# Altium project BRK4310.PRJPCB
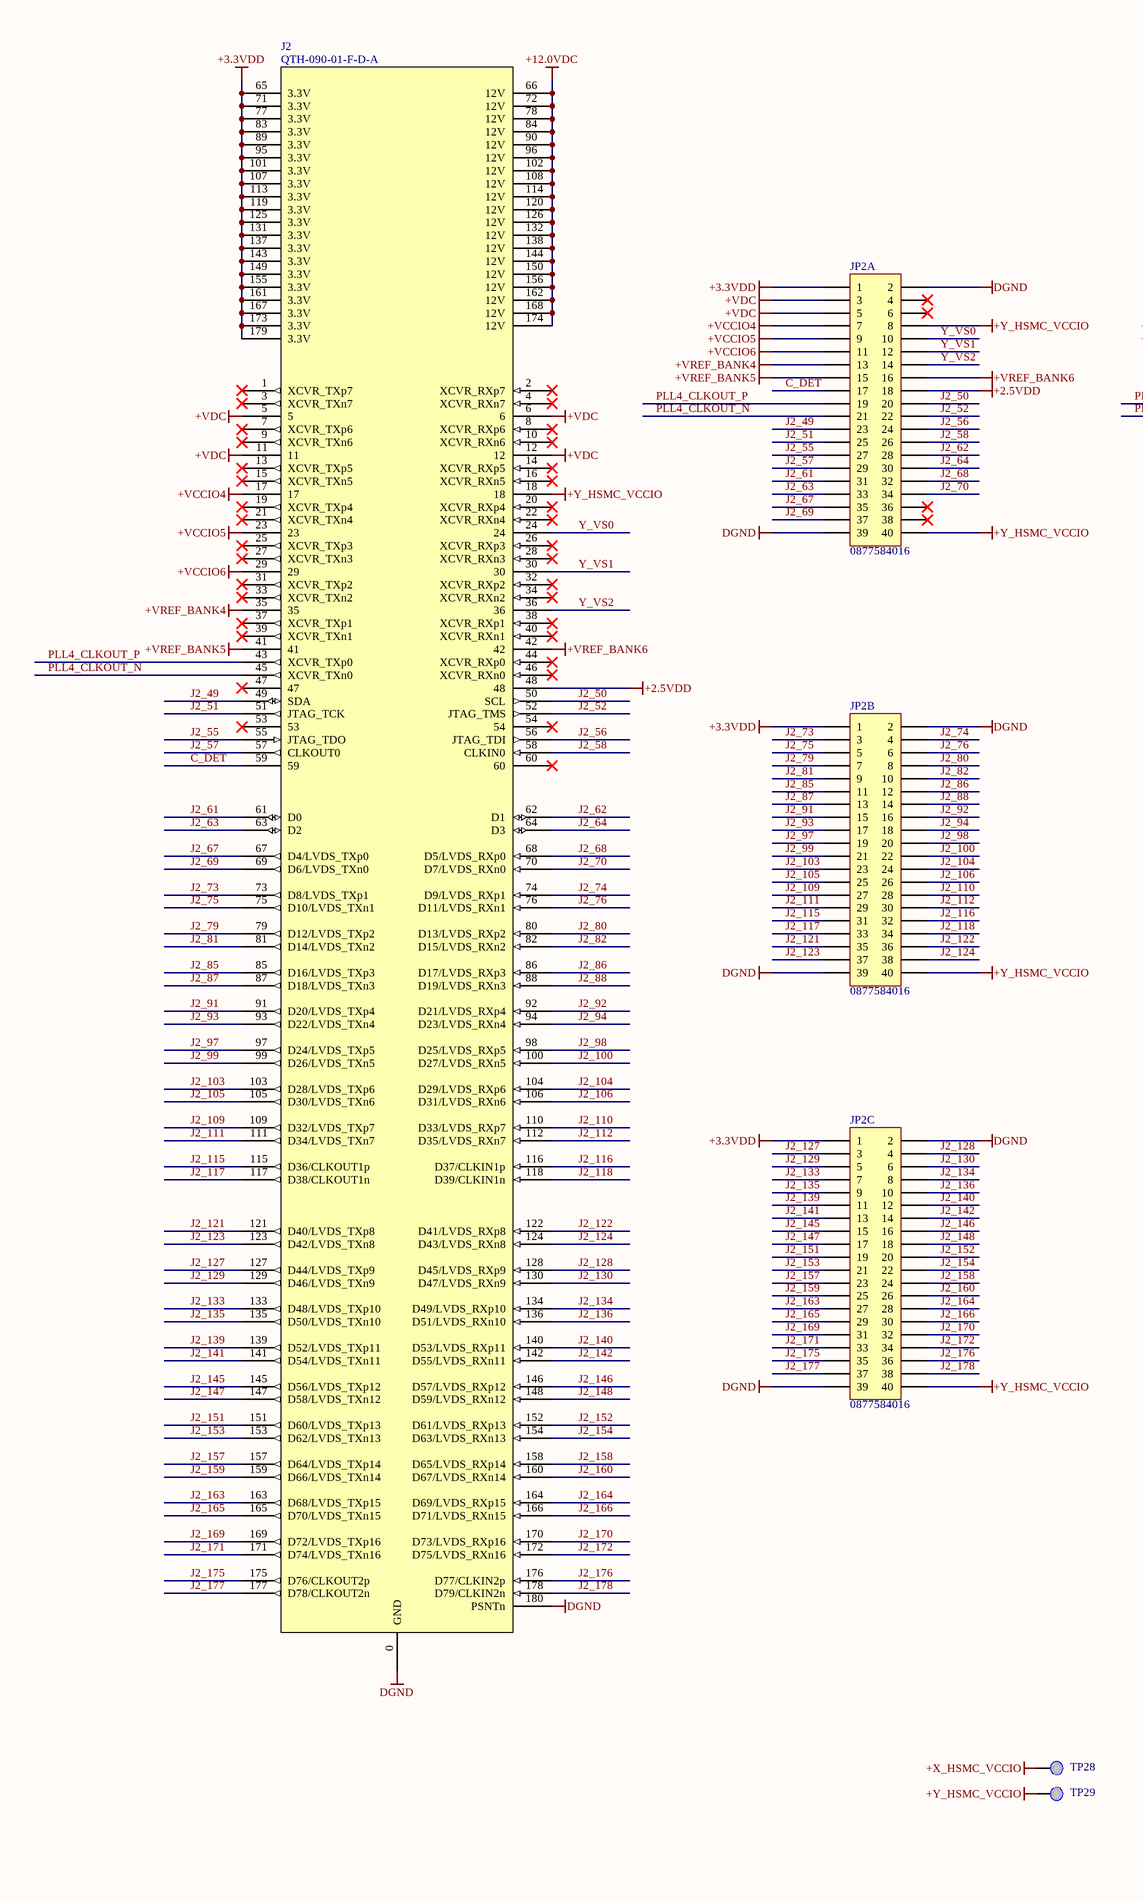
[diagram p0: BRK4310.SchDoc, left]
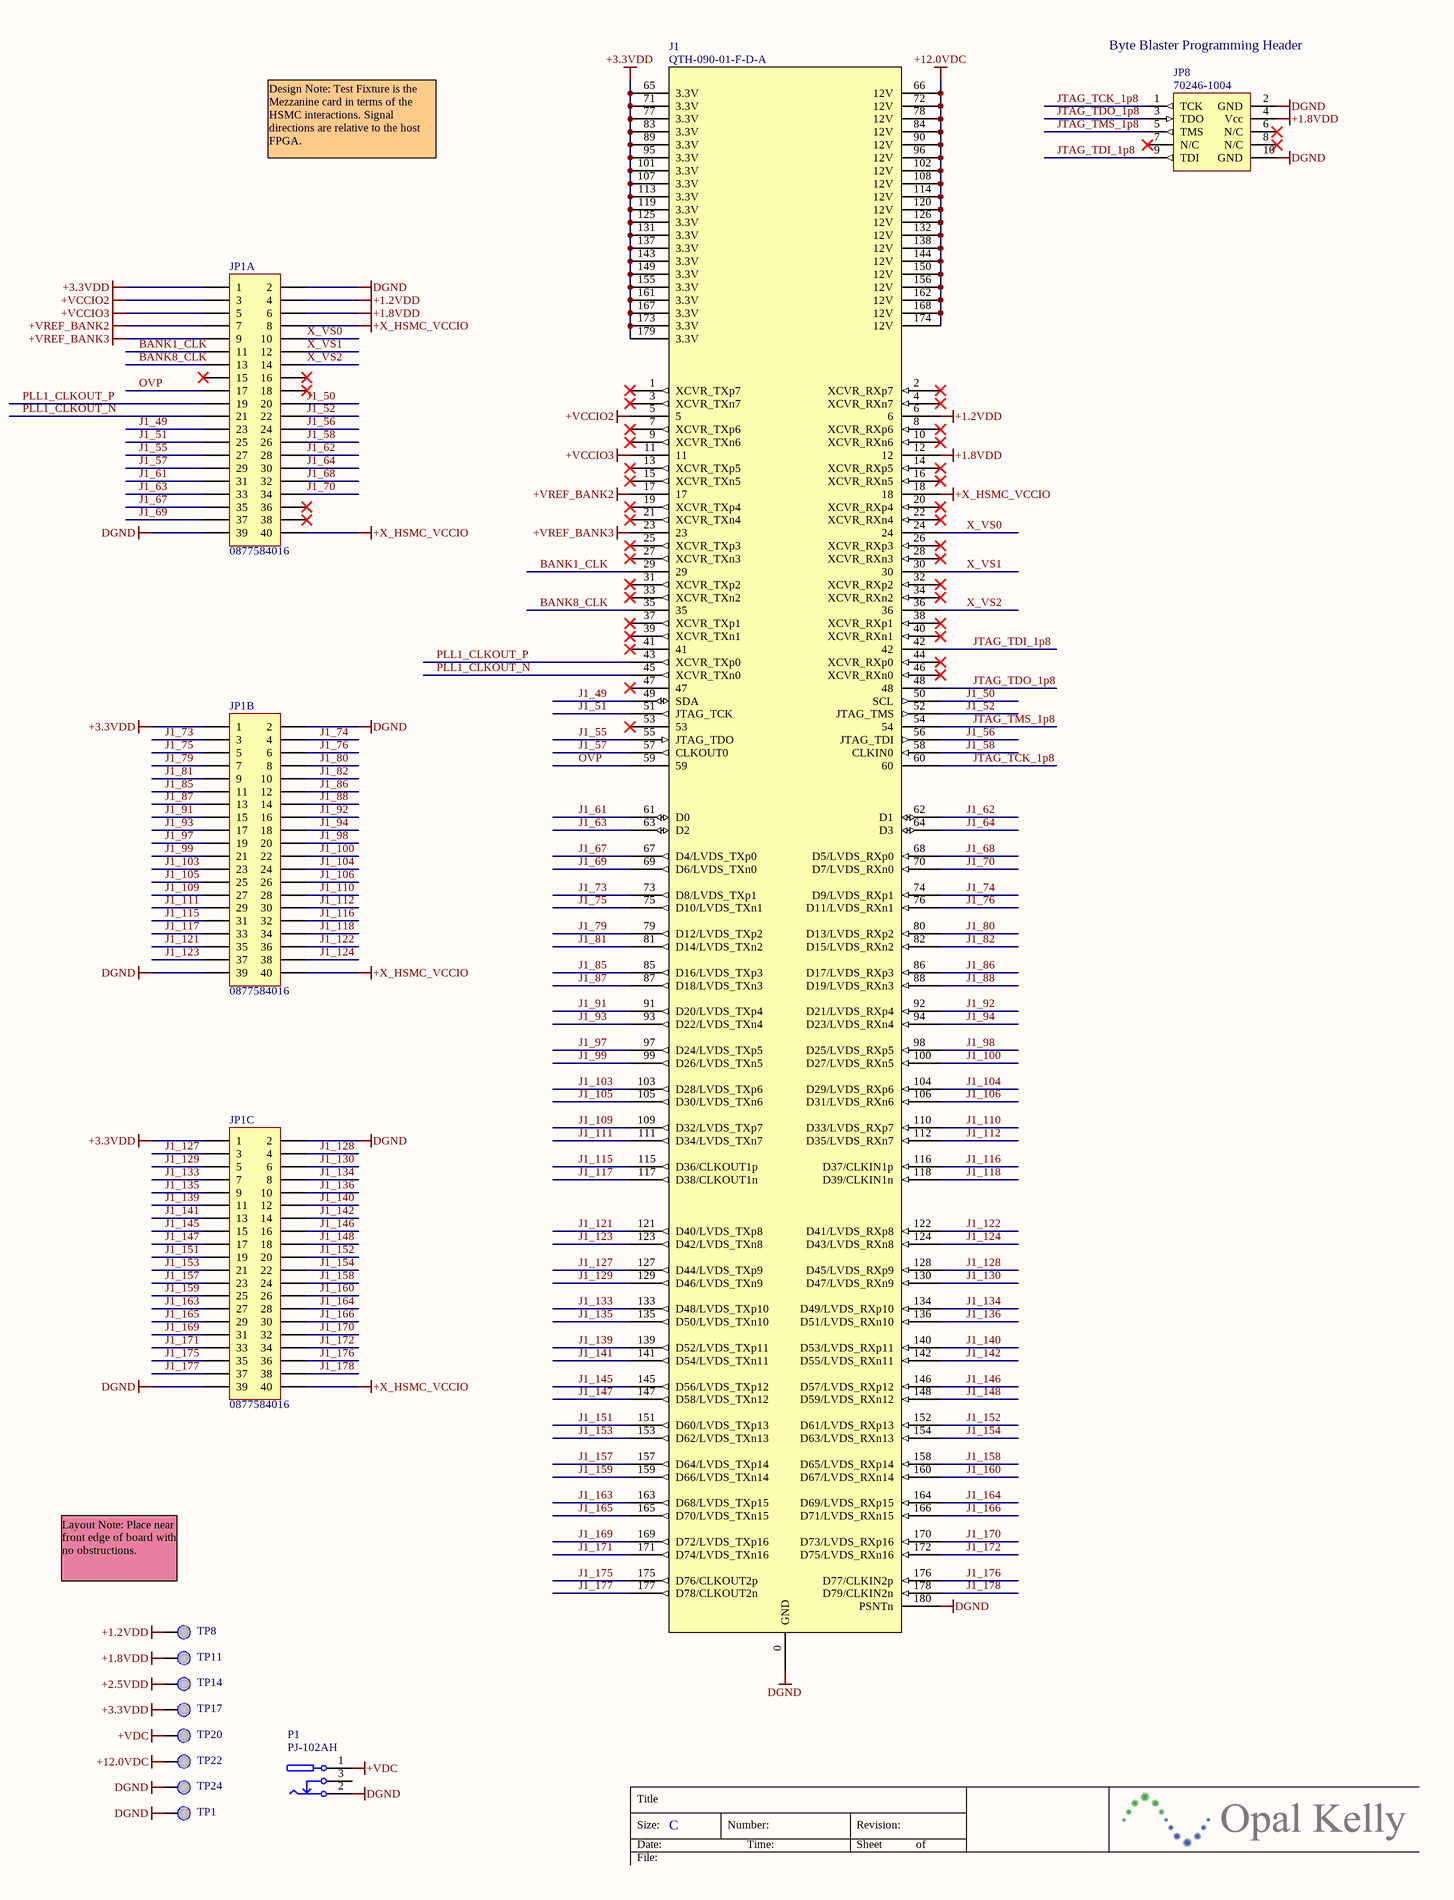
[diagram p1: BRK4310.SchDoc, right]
1 sheet, 20 parts. Net scope: global (net labels, ports and power ports of the same name join across sheets).
Board file: BRK4310.PcbDoc

## Sheet BRK4310.SchDoc: BRK4310
size C; Author: Jake Janovetz; Organization: Opal Kelly; Address1: 13500 SW 72nd Ave, STE 120; Address2: Portland, OR 97223; Address4: http://www.opalkelly.com; DocumentNumber: xxx; Revision: 1; SheetNumber: 1; SheetTotal: 1; PageSetup: Record=PageOptions¦CenterHorizontal=True¦CenterVertical=True¦PrintScale=0.53¦XCorrection=1.00¦YCorrection=1.00¦PrintKind=0¦BorderSize=5000000¦LeftOffset=0¦BottomOffset=0¦Orientation=2¦PaperLength=1000¦PaperWidth=1000¦Scale=100¦PaperSource=7¦PrintQuality=-4¦MediaType=1¦DitherType=10¦PaperKind=Letter¦PrintScaleMode=1

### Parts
J1  QTH-090-01-F-D-A  [QTH-090-01-X-D]
J2  QTH-090-01-F-D-A  [QTH-090-01-X-D]
JP1A  0877584016  [HDR2X20-2MM]
JP1B  0877584016  [HDR2X20-2MM]
JP1C  0877584016  [HDR2X20-2MM]
JP2A  0877584016  [HDR2X20-2MM]
JP2B  0877584016  [HDR2X20-2MM]
JP2C  0877584016  [HDR2X20-2MM]
JP8  70246-1004  [HDR2X5-SHRD]
P1  PJ-102AH  [CUI-PJ102A]
TP1  DGND  [TP_MED]  (value not drawn)
TP8  +1.2VDD  [TP_MED]  (value not drawn)
TP11  +1.8VDD  [TP_MED]  (value not drawn)
TP14  +2.5VDD  [TP_MED]  (value not drawn)
TP17  +3.3VDD  [TP_MED]  (value not drawn)
TP20  +VDC  [TP_MED]  (value not drawn)
TP22  +12.0VDC  [TP_MED]  (value not drawn)
TP24  DGND  [TP_MED]  (value not drawn)
TP28  +J1_VCCIO  [TP_MED]  (value not drawn)
TP29  +J2_VCCIO  [TP_MED]  (value not drawn)

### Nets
+1.2VDD: J1.6 JP1A.4 TP8.1(PIN)
+1.8VDD: J1.12 JP1A.6 JP8.4(Vcc) TP11.1(PIN)
+2.5VDD: J2.48 JP2A.18 TP14.1(PIN)
+3.3VDD: J1.65(3.3V) J1.71(3.3V) J1.77(3.3V) J1.83(3.3V) J1.89(3.3V) J1.95(3.3V) J1.101(3.3V) J1.107(3.3V) J1.113(3.3V) J1.119(3.3V) J1.125(3.3V) J1.131(3.3V) J1.137(3.3V) J1.143(3.3V) J1.149(3.3V) J1.155(3.3V) J1.161(3.3V) J1.167(3.3V) J1.173(3.3V) J1.179(3.3V) J2.65(3.3V) J2.71(3.3V) J2.77(3.3V) J2.83(3.3V) J2.89(3.3V) J2.95(3.3V) J2.101(3.3V) J2.107(3.3V) J2.113(3.3V) J2.119(3.3V) J2.125(3.3V) J2.131(3.3V) J2.137(3.3V) J2.143(3.3V) J2.149(3.3V) J2.155(3.3V) J2.161(3.3V) J2.167(3.3V) J2.173(3.3V) J2.179(3.3V) JP1A.1 JP1B.1 JP1C.1 JP2A.1 JP2B.1 JP2C.1 TP17.1(PIN)
+12.0VDC: J1.66(12V) J1.72(12V) J1.78(12V) J1.84(12V) J1.90(12V) J1.96(12V) J1.102(12V) J1.108(12V) J1.114(12V) J1.120(12V) J1.126(12V) J1.132(12V) J1.138(12V) J1.144(12V) J1.150(12V) J1.156(12V) J1.162(12V) J1.168(12V) J1.174(12V) J2.66(12V) J2.72(12V) J2.78(12V) J2.84(12V) J2.90(12V) J2.96(12V) J2.102(12V) J2.108(12V) J2.114(12V) J2.120(12V) J2.126(12V) J2.132(12V) J2.138(12V) J2.144(12V) J2.150(12V) J2.156(12V) J2.162(12V) J2.168(12V) J2.174(12V) TP22.1(PIN)
+VCCIO2: J1.5 JP1A.3
+VCCIO3: J1.11 JP1A.5
+VCCIO4: J2.17 JP2A.7
+VCCIO5: J2.23 JP2A.9
+VCCIO6: J2.29 JP2A.11
+VDC: J2.5 J2.6 J2.11 J2.12 JP2A.3 JP2A.5 P1.1 TP20.1(PIN)
+VREF_BANK2: J1.17 JP1A.7
+VREF_BANK3: J1.23 JP1A.9
+VREF_BANK4: J2.35 JP2A.13
+VREF_BANK5: J2.41 JP2A.15
+VREF_BANK6: J2.42 JP2A.16
+X_HSMC_VCCIO: J1.18 JP1A.8 JP1A.40 JP1B.40 JP1C.40 TP28.1(PIN)
+Y_HSMC_VCCIO: J2.18 JP2A.8 JP2A.40 JP2B.40 JP2C.40 TP29.1(PIN)
DGND: J1.0(GND) J1.180(PSNTn) J2.0(GND) J2.180(PSNTn) JP1A.2 JP1A.39 JP1B.2 JP1B.39 JP1C.2 JP1C.39 JP2A.2 JP2A.39 JP2B.2 JP2B.39 JP2C.2 JP2C.39 JP8.2(GND) JP8.10(GND) P1.2 TP1.1(PIN) TP24.1(PIN)
BANK1_CLK: J1.29 JP1A.11
BANK8_CLK: J1.35 JP1A.13
C_DET: J2.59 JP2A.17
J1_49: J1.49(SDA) JP1A.23
J1_50: J1.50(SCL) JP1A.20
J1_51: J1.51(JTAG_TCK) JP1A.25
J1_52: J1.52(JTAG_TMS) JP1A.22
J1_55: J1.55(JTAG_TDO) JP1A.27
J1_56: J1.56(JTAG_TDI) JP1A.24
J1_57: J1.57(CLKOUT0) JP1A.29
J1_58: J1.58(CLKIN0) JP1A.26
J1_61: J1.61(D0) JP1A.31
J1_62: J1.62(D1) JP1A.28
J1_63: J1.63(D2) JP1A.33
J1_64: J1.64(D3) JP1A.30
J1_67: J1.67(D4/LVDS_TXp0) JP1A.35
J1_68: J1.68(D5/LVDS_RXp0) JP1A.32
J1_69: J1.69(D6/LVDS_TXn0) JP1A.37
J1_70: J1.70(D7/LVDS_RXn0) JP1A.34
J1_73: J1.73(D8/LVDS_TXp1) JP1B.3
J1_74: J1.74(D9/LVDS_RXp1) JP1B.4
J1_75: J1.75(D10/LVDS_TXn1) JP1B.5
J1_76: J1.76(D11/LVDS_RXn1) JP1B.6
J1_79: J1.79(D12/LVDS_TXp2) JP1B.7
J1_80: J1.80(D13/LVDS_RXp2) JP1B.8
J1_81: J1.81(D14/LVDS_TXn2) JP1B.9
J1_82: J1.82(D15/LVDS_RXn2) JP1B.10
J1_85: J1.85(D16/LVDS_TXp3) JP1B.11
J1_86: J1.86(D17/LVDS_RXp3) JP1B.12
J1_87: J1.87(D18/LVDS_TXn3) JP1B.13
J1_88: J1.88(D19/LVDS_RXn3) JP1B.14
J1_91: J1.91(D20/LVDS_TXp4) JP1B.15
J1_92: J1.92(D21/LVDS_RXp4) JP1B.16
J1_93: J1.93(D22/LVDS_TXn4) JP1B.17
J1_94: J1.94(D23/LVDS_RXn4) JP1B.18
J1_97: J1.97(D24/LVDS_TXp5) JP1B.19
J1_98: J1.98(D25/LVDS_RXp5) JP1B.20
J1_99: J1.99(D26/LVDS_TXn5) JP1B.21
J1_100: J1.100(D27/LVDS_RXn5) JP1B.22
J1_103: J1.103(D28/LVDS_TXp6) JP1B.23
J1_104: J1.104(D29/LVDS_RXp6) JP1B.24
J1_105: J1.105(D30/LVDS_TXn6) JP1B.25
J1_106: J1.106(D31/LVDS_RXn6) JP1B.26
J1_109: J1.109(D32/LVDS_TXp7) JP1B.27
J1_110: J1.110(D33/LVDS_RXp7) JP1B.28
J1_111: J1.111(D34/LVDS_TXn7) JP1B.29
J1_112: J1.112(D35/LVDS_RXn7) JP1B.30
J1_115: J1.115(D36/CLKOUT1p) JP1B.31
J1_116: J1.116(D37/CLKIN1p) JP1B.32
J1_117: J1.117(D38/CLKOUT1n) JP1B.33
J1_118: J1.118(D39/CLKIN1n) JP1B.34
J1_121: J1.121(D40/LVDS_TXp8) JP1B.35
J1_122: J1.122(D41/LVDS_RXp8) JP1B.36
J1_123: J1.123(D42/LVDS_TXn8) JP1B.37
J1_124: J1.124(D43/LVDS_RXn8) JP1B.38
J1_127: J1.127(D44/LVDS_TXp9) JP1C.3
J1_128: J1.128(D45/LVDS_RXp9) JP1C.4
J1_129: J1.129(D46/LVDS_TXn9) JP1C.5
J1_130: J1.130(D47/LVDS_RXn9) JP1C.6
J1_133: J1.133(D48/LVDS_TXp10) JP1C.7
J1_134: J1.134(D49/LVDS_RXp10) JP1C.8
J1_135: J1.135(D50/LVDS_TXn10) JP1C.9
J1_136: J1.136(D51/LVDS_RXn10) JP1C.10
J1_139: J1.139(D52/LVDS_TXp11) JP1C.11
J1_140: J1.140(D53/LVDS_RXp11) JP1C.12
J1_141: J1.141(D54/LVDS_TXn11) JP1C.13
J1_142: J1.142(D55/LVDS_RXn11) JP1C.14
J1_145: J1.145(D56/LVDS_TXp12) JP1C.15
J1_146: J1.146(D57/LVDS_RXp12) JP1C.16
J1_147: J1.147(D58/LVDS_TXn12) JP1C.17
J1_148: J1.148(D59/LVDS_RXn12) JP1C.18
J1_151: J1.151(D60/LVDS_TXp13) JP1C.19
J1_152: J1.152(D61/LVDS_RXp13) JP1C.20
J1_153: J1.153(D62/LVDS_TXn13) JP1C.21
J1_154: J1.154(D63/LVDS_RXn13) JP1C.22
J1_157: J1.157(D64/LVDS_TXp14) JP1C.23
J1_158: J1.158(D65/LVDS_RXp14) JP1C.24
J1_159: J1.159(D66/LVDS_TXn14) JP1C.25
J1_160: J1.160(D67/LVDS_RXn14) JP1C.26
J1_163: J1.163(D68/LVDS_TXp15) JP1C.27
J1_164: J1.164(D69/LVDS_RXp15) JP1C.28
J1_165: J1.165(D70/LVDS_TXn15) JP1C.29
J1_166: J1.166(D71/LVDS_RXn15) JP1C.30
J1_169: J1.169(D72/LVDS_TXp16) JP1C.31
J1_170: J1.170(D73/LVDS_RXp16) JP1C.32
J1_171: J1.171(D74/LVDS_TXn16) JP1C.33
J1_172: J1.172(D75/LVDS_RXn16) JP1C.34
J1_175: J1.175(D76/CLKOUT2p) JP1C.35
J1_176: J1.176(D77/CLKIN2p) JP1C.36
J1_177: J1.177(D78/CLKOUT2n) JP1C.37
J1_178: J1.178(D79/CLKIN2n) JP1C.38
J2_49: J2.49(SDA) JP2A.23
J2_50: J2.50(SCL) JP2A.20
J2_51: J2.51(JTAG_TCK) JP2A.25
J2_52: J2.52(JTAG_TMS) JP2A.22
J2_55: J2.55(JTAG_TDO) JP2A.27
J2_56: J2.56(JTAG_TDI) JP2A.24
J2_57: J2.57(CLKOUT0) JP2A.29
J2_58: J2.58(CLKIN0) JP2A.26
J2_61: J2.61(D0) JP2A.31
J2_62: J2.62(D1) JP2A.28
J2_63: J2.63(D2) JP2A.33
J2_64: J2.64(D3) JP2A.30
J2_67: J2.67(D4/LVDS_TXp0) JP2A.35
J2_68: J2.68(D5/LVDS_RXp0) JP2A.32
J2_69: J2.69(D6/LVDS_TXn0) JP2A.37
J2_70: J2.70(D7/LVDS_RXn0) JP2A.34
J2_73: J2.73(D8/LVDS_TXp1) JP2B.3
J2_74: J2.74(D9/LVDS_RXp1) JP2B.4
J2_75: J2.75(D10/LVDS_TXn1) JP2B.5
J2_76: J2.76(D11/LVDS_RXn1) JP2B.6
J2_79: J2.79(D12/LVDS_TXp2) JP2B.7
J2_80: J2.80(D13/LVDS_RXp2) JP2B.8
J2_81: J2.81(D14/LVDS_TXn2) JP2B.9
J2_82: J2.82(D15/LVDS_RXn2) JP2B.10
J2_85: J2.85(D16/LVDS_TXp3) JP2B.11
J2_86: J2.86(D17/LVDS_RXp3) JP2B.12
J2_87: J2.87(D18/LVDS_TXn3) JP2B.13
J2_88: J2.88(D19/LVDS_RXn3) JP2B.14
J2_91: J2.91(D20/LVDS_TXp4) JP2B.15
J2_92: J2.92(D21/LVDS_RXp4) JP2B.16
J2_93: J2.93(D22/LVDS_TXn4) JP2B.17
J2_94: J2.94(D23/LVDS_RXn4) JP2B.18
J2_97: J2.97(D24/LVDS_TXp5) JP2B.19
J2_98: J2.98(D25/LVDS_RXp5) JP2B.20
J2_99: J2.99(D26/LVDS_TXn5) JP2B.21
J2_100: J2.100(D27/LVDS_RXn5) JP2B.22
J2_103: J2.103(D28/LVDS_TXp6) JP2B.23
J2_104: J2.104(D29/LVDS_RXp6) JP2B.24
J2_105: J2.105(D30/LVDS_TXn6) JP2B.25
J2_106: J2.106(D31/LVDS_RXn6) JP2B.26
J2_109: J2.109(D32/LVDS_TXp7) JP2B.27
J2_110: J2.110(D33/LVDS_RXp7) JP2B.28
J2_111: J2.111(D34/LVDS_TXn7) JP2B.29
J2_112: J2.112(D35/LVDS_RXn7) JP2B.30
J2_115: J2.115(D36/CLKOUT1p) JP2B.31
J2_116: J2.116(D37/CLKIN1p) JP2B.32
J2_117: J2.117(D38/CLKOUT1n) JP2B.33
J2_118: J2.118(D39/CLKIN1n) JP2B.34
J2_121: J2.121(D40/LVDS_TXp8) JP2B.35
J2_122: J2.122(D41/LVDS_RXp8) JP2B.36
J2_123: J2.123(D42/LVDS_TXn8) JP2B.37
J2_124: J2.124(D43/LVDS_RXn8) JP2B.38
J2_127: J2.127(D44/LVDS_TXp9) JP2C.3
J2_128: J2.128(D45/LVDS_RXp9) JP2C.4
J2_129: J2.129(D46/LVDS_TXn9) JP2C.5
J2_130: J2.130(D47/LVDS_RXn9) JP2C.6
J2_133: J2.133(D48/LVDS_TXp10) JP2C.7
J2_134: J2.134(D49/LVDS_RXp10) JP2C.8
J2_135: J2.135(D50/LVDS_TXn10) JP2C.9
J2_136: J2.136(D51/LVDS_RXn10) JP2C.10
J2_139: J2.139(D52/LVDS_TXp11) JP2C.11
J2_140: J2.140(D53/LVDS_RXp11) JP2C.12
J2_141: J2.141(D54/LVDS_TXn11) JP2C.13
J2_142: J2.142(D55/LVDS_RXn11) JP2C.14
J2_145: J2.145(D56/LVDS_TXp12) JP2C.15
J2_146: J2.146(D57/LVDS_RXp12) JP2C.16
J2_147: J2.147(D58/LVDS_TXn12) JP2C.17
J2_148: J2.148(D59/LVDS_RXn12) JP2C.18
J2_151: J2.151(D60/LVDS_TXp13) JP2C.19
J2_152: J2.152(D61/LVDS_RXp13) JP2C.20
J2_153: J2.153(D62/LVDS_TXn13) JP2C.21
J2_154: J2.154(D63/LVDS_RXn13) JP2C.22
J2_157: J2.157(D64/LVDS_TXp14) JP2C.23
J2_158: J2.158(D65/LVDS_RXp14) JP2C.24
J2_159: J2.159(D66/LVDS_TXn14) JP2C.25
J2_160: J2.160(D67/LVDS_RXn14) JP2C.26
J2_163: J2.163(D68/LVDS_TXp15) JP2C.27
J2_164: J2.164(D69/LVDS_RXp15) JP2C.28
J2_165: J2.165(D70/LVDS_TXn15) JP2C.29
J2_166: J2.166(D71/LVDS_RXn15) JP2C.30
J2_169: J2.169(D72/LVDS_TXp16) JP2C.31
J2_170: J2.170(D73/LVDS_RXp16) JP2C.32
J2_171: J2.171(D74/LVDS_TXn16) JP2C.33
J2_172: J2.172(D75/LVDS_RXn16) JP2C.34
J2_175: J2.175(D76/CLKOUT2p) JP2C.35
J2_176: J2.176(D77/CLKIN2p) JP2C.36
J2_177: J2.177(D78/CLKOUT2n) JP2C.37
J2_178: J2.178(D79/CLKIN2n) JP2C.38
JTAG_TCK_1p8: J1.60 JP8.1(TCK)
JTAG_TDI_1p8: J1.42 JP8.9(TDI)
JTAG_TDO_1p8: J1.48 JP8.3(TDO)
JTAG_TMS_1p8: J1.54 JP8.5(TMS)
OVP: J1.59 JP1A.17
PLL1_CLKOUT_N: J1.45(XCVR_TXn0) JP1A.21
PLL1_CLKOUT_P: J1.43(XCVR_TXp0) JP1A.19
PLL4_CLKOUT_N: J2.45(XCVR_TXn0) JP2A.21
PLL4_CLKOUT_P: J2.43(XCVR_TXp0) JP2A.19
X_VS0: J1.24 JP1A.10
X_VS1: J1.30 JP1A.12
X_VS2: J1.36 JP1A.14
Y_VS0: J2.24 JP2A.10
Y_VS1: J2.30 JP2A.12
Y_VS2: J2.36 JP2A.14

Not connected (* = marked no-connect by the designer): J1 1(XCVR_TXp7)* 2(XCVR_RXp7)* 3(XCVR_TXn7)* 4(XCVR_RXn7)* 7(XCVR_TXp6)* 8(XCVR_RXp6)* 9(XCVR_TXn6)* 10(XCVR_RXn6)* 13(XCVR_TXp5)* 14(XCVR_RXp5)* 15(XCVR_TXn5)* 16(XCVR_RXn5)* 19(XCVR_TXp4)* 20(XCVR_RXp4)* 21(XCVR_TXn4)* 22(XCVR_RXn4)* 25(XCVR_TXp3)* 26(XCVR_RXp3)* 27(XCVR_TXn3)* 28(XCVR_RXn3)* 31(XCVR_TXp2)* 32(XCVR_RXp2)* 33(XCVR_TXn2)* 34(XCVR_RXn2)* 37(XCVR_TXp1)* 38(XCVR_RXp1)* 39(XCVR_TXn1)* 40(XCVR_RXn1)* 41* 44(XCVR_RXp0)* 46(XCVR_RXn0)* 47* 53*; J2 1(XCVR_TXp7)* 2(XCVR_RXp7)* 3(XCVR_TXn7)* 4(XCVR_RXn7)* 7(XCVR_TXp6)* 8(XCVR_RXp6)* 9(XCVR_TXn6)* 10(XCVR_RXn6)* 13(XCVR_TXp5)* 14(XCVR_RXp5)* 15(XCVR_TXn5)* 16(XCVR_RXn5)* 19(XCVR_TXp4)* 20(XCVR_RXp4)* 21(XCVR_TXn4)* 22(XCVR_RXn4)* 25(XCVR_TXp3)* 26(XCVR_RXp3)* 27(XCVR_TXn3)* 28(XCVR_RXn3)* 31(XCVR_TXp2)* 32(XCVR_RXp2)* 33(XCVR_TXn2)* 34(XCVR_RXn2)* 37(XCVR_TXp1)* 38(XCVR_RXp1)* 39(XCVR_TXn1)* 40(XCVR_RXn1)* 44(XCVR_RXp0)* 46(XCVR_RXn0)* 47* 53* 54* 60*; JP1A 15* 16* 18* 36* 38*; JP2A 4* 6* 36* 38*; JP8 6(N/C)* 7(N/C)* 8(N/C)*; P1 3

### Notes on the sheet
- Byte Blaster Programming Header
- Design Note: Test Fixture is the Mezzanine card in terms of the HSMC interactions. Signal directions are relative to the host FPGA.
- Layout Note: Place near front edge of board with no obstructions.
- Title
- Size:
- Date:
- File:
- C
- Number:
- Time:
- Revision:
- Sheet
- of

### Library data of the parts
J1 J2 = 000876: 0.5mm hi-speed, high-density header (Female); Manufacturer: Samtec; partnumber: 000876; Description 2: 180-pin, ground plane in middle
JP1A JP1B JP1C JP2A JP2B JP2C = 000583: 2mm header, 20x2, thru-hole; Manufacturer: Molex; partnumber: 000583
JP8 = 000777: 2.54mm, 10 Pos, Dual Row Header; Manufacturer: Molex; partnumber: 000777; Description 2: Altera JTAG Compatible
P1 = 000356: DC power connector - high current; Manufacturer: CUI Inc.; partnumber: 000356; Description 2: 2.1mm / 5.5mm
TP1 TP8 TP11 TP14 TP17 TP20 TP22 TP24 TP28 TP29 = 000812: Testpoint.; Manufacturer: Opal Kelly Incorporated; Manufacturer_PN: PCB-TESTPOINT; partnumber: 000812; x_pcb_footprint_4: TP_SMD40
